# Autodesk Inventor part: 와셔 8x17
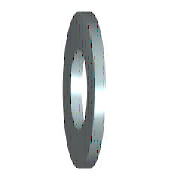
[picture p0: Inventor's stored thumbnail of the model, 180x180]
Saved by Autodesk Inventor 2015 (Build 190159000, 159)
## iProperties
IsCustomPart: 1
Created: 2012-02
Part Number: 와셔 8x17
Material: 강철, 연강
Description: 평면 와셔
Document SubType Name: Modeling
Standard: KS B 1326
Designer: mduedu
Standards Organization: KS
Language: ko-KR
Size Designation: 8x17
Categories: <MemberInstance><Categories><Category DisplayName="조임쇠" InternalName="e4da775c-781d-43d5-af7c-5136215cf5a6" Mnemonic="FSTN"><Category DisplayName="와셔" InternalN
Density: 1 g/cm^3
Appearance: 주황색
Author: mduedu
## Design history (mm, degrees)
sketch "스케치"
  geometry: C1 r 8.5 at (0, 0); C2 r 4.2 at (0, 0); 1 further point
  constraints: 2 centre point, 2 coincident
  dimensions: "d0" = 8.4 diameter of C2 (= SD1); "d1" = 17 diameter of C1 (= SD2)
extrude "본체" new body sketch "스케치" distance "d2" = 1.6 (= SD); taper "d3" = 0 deg
workaxis "Work Axis1"
workplane "Work Plane1"
body "Solid1"
other parameters: "SD1" = 8.4 [user parameter; used in 1 equation term], "SD2" = 17 [user parameter; used in 1 equation term], "SD" = 1.6 [user parameter; used in 1 equation term], "d4" = 0, "d5" = 0, "d6" = 0, "d7" = 0, "NND" = 8 [user parameter]
